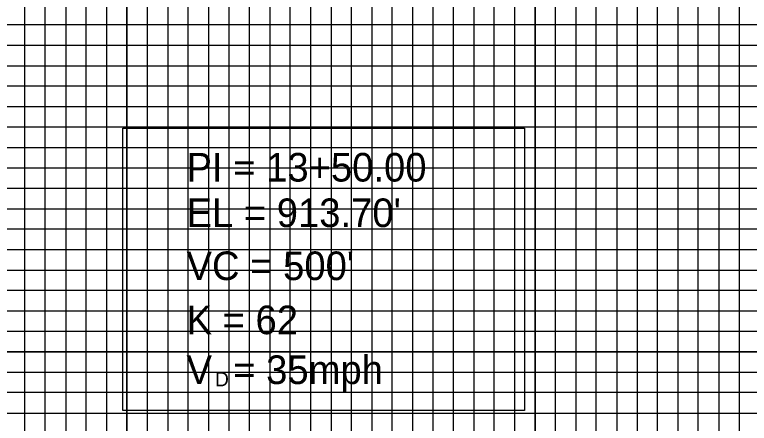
# Model space of a CAD drawing. Extents: x 573624 to 575507, y -53727 to -52273.
# Drawn here: x 574463.3 to 574643.3, y -52790.6 to -52690.6 of the extents above; entities that cross this region are included whole.
import ezdxf

# ---------------------------------------------------------------- set-up
doc = ezdxf.new("R2010")
doc.units = 0
for name, color, linetype in [('Prop Grid Mask', 7, 'Continuous'), ('Prop Vertical Profile Curve Label', 7, 'Continuous'), ('Prop VPI Label', 7, 'Continuous'), ('Sheet DOT Grid CELL', 7, 'Continuous'), ('Sheet Profile Grid Major CELL', 7, 'Continuous'), ('Sheet Profile Grid Middle CELL', 7, 'Continuous'), ('Sheet Profile Grid Minor CELL', 7, 'Continuous')]:
    doc.layers.add(name, color=color, linetype=linetype)

msp = doc.modelspace()

# ---------------------------------------------------------------- linework, layer by layer
at = {"layer": 'Prop Grid Mask'}
msp.add_lwpolyline([(574489.76, -52718.32), (574588.22, -52718.32), (574588.22, -52787.47), (574489.76, -52787.47)], close=True, dxfattribs=at)
at = {"layer": 'Sheet DOT Grid CELL'}
for p, q in [((574490.78, -52298.09), (574490.78, -53323.09)), ((574540.78, -52298.09), (574540.78, -53323.09)), ((574590.78, -52298.09), (574590.78, -53323.09)), ((574640.78, -52298.09), (574640.78, -53323.09)), ((573790.78, -52723.09), (575290.78, -52723.09)), ((573790.78, -52773.09), (575290.78, -52773.09))]:
    msp.add_line(p, q, dxfattribs=at)
at = {"layer": 'Sheet Profile Grid Major CELL'}
for points in [[(574490.78, -53323.09), (574490.78, -52298.09), (574540.78, -52298.09), (574540.78, -53323.09)], [(574590.78, -53323.09), (574590.78, -52298.09), (574640.78, -52298.09), (574640.78, -53323.09)], [(575290.78, -52773.09), (573790.78, -52773.09), (573790.78, -52723.09), (575290.78, -52723.09)]]:
    msp.add_lwpolyline(points, dxfattribs=at)
at = {"layer": 'Sheet Profile Grid Middle CELL'}
for points in [[(574465.78, -53323.09), (574465.78, -52298.09), (574515.78, -52298.09), (574515.78, -53323.09)], [(574565.78, -53323.09), (574565.78, -52298.09), (574615.78, -52298.09), (574615.78, -53323.09)], [(575290.78, -52698.09), (573790.78, -52698.09), (573790.78, -52748.09), (575290.78, -52748.09)]]:
    msp.add_lwpolyline(points, dxfattribs=at)
at = {"layer": 'Sheet Profile Grid Minor CELL'}
for points in [[(574470.78, -53323.09), (574470.78, -52298.09), (574475.78, -52298.09), (574475.78, -53323.09)], [(574480.78, -53323.09), (574480.78, -52298.09), (574485.78, -52298.09), (574485.78, -53323.09)], [(574495.78, -53323.09), (574495.78, -52298.09), (574500.78, -52298.09), (574500.78, -53323.09)], [(574505.78, -53323.09), (574505.78, -52298.09), (574510.78, -52298.09), (574510.78, -53323.09)], [(574520.78, -53323.09), (574520.78, -52298.09), (574525.78, -52298.09), (574525.78, -53323.09)], [(574530.78, -53323.09), (574530.78, -52298.09), (574535.78, -52298.09), (574535.78, -53323.09)], [(574545.78, -53323.09), (574545.78, -52298.09), (574550.78, -52298.09), (574550.78, -53323.09)], [(574555.78, -53323.09), (574555.78, -52298.69), (574560.78, -52298.69), (574560.78, -53323.09)], [(574570.78, -53323.09), (574570.78, -52298.09), (574575.78, -52298.09), (574575.78, -53323.09)], [(574580.78, -53323.09), (574580.78, -52298.09), (574585.78, -52298.09), (574585.78, -53323.09)], [(574595.78, -53323.09), (574595.78, -52298.09), (574600.78, -52298.09), (574600.78, -53323.09)], [(574605.78, -53323.09), (574605.78, -52298.09), (574610.78, -52298.09), (574610.78, -53323.09)], [(574620.78, -53323.09), (574620.78, -52298.09), (574625.78, -52298.09), (574625.78, -53323.09)], [(574630.78, -53323.09), (574630.78, -52298.09), (574635.78, -52298.09), (574635.78, -53323.09)], [(575240.78, -52693.09), (573840.78, -52693.09), (573840.78, -52703.09), (575240.78, -52703.09)], [(575240.78, -52708.09), (573840.78, -52708.09), (573840.78, -52713.09), (575240.78, -52713.09)], [(575240.78, -52718.09), (573840.78, -52718.09), (573840.78, -52728.09), (575240.78, -52728.09)], [(575240.78, -52733.09), (573840.78, -52733.09), (573840.78, -52738.09), (575240.78, -52738.09)], [(575240.78, -52743.09), (573840.78, -52743.09), (573840.78, -52753.09), (575240.78, -52753.09)], [(575240.78, -52758.09), (573840.78, -52758.09), (573840.78, -52763.09), (575240.78, -52763.09)], [(575240.78, -52768.09), (573840.78, -52768.09), (573840.78, -52778.09), (575240.78, -52778.09)], [(575240.78, -52783.09), (573840.78, -52783.09), (573840.78, -52788.09), (575240.78, -52788.09)]]:
    msp.add_lwpolyline(points, dxfattribs=at)

# ---------------------------------------------------------------- texts
at = {"layer": 'Prop Vertical Profile Curve Label'}
for s, height, p in [("VC = 500'", 7, (574505.37, -52755.54)), ('K = 62', 7, (574505.37, -52768.78)), ('V  = 35mph', 7, (574505.37, -52780.98)), ('D', 3.5, (574512.37, -52781.54))]:
    msp.add_text(s, height=height, dxfattribs=at).set_placement(p)
at = {"layer": 'Prop VPI Label'}
for s, p in [('PI = 13+50.00', (574505.37, -52731.42)), ("EL = 913.70'", (574505.37, -52742.56))]:
    msp.add_text(s, height=7, dxfattribs=at).set_placement(p)

doc.saveas('drawing.dxf')
